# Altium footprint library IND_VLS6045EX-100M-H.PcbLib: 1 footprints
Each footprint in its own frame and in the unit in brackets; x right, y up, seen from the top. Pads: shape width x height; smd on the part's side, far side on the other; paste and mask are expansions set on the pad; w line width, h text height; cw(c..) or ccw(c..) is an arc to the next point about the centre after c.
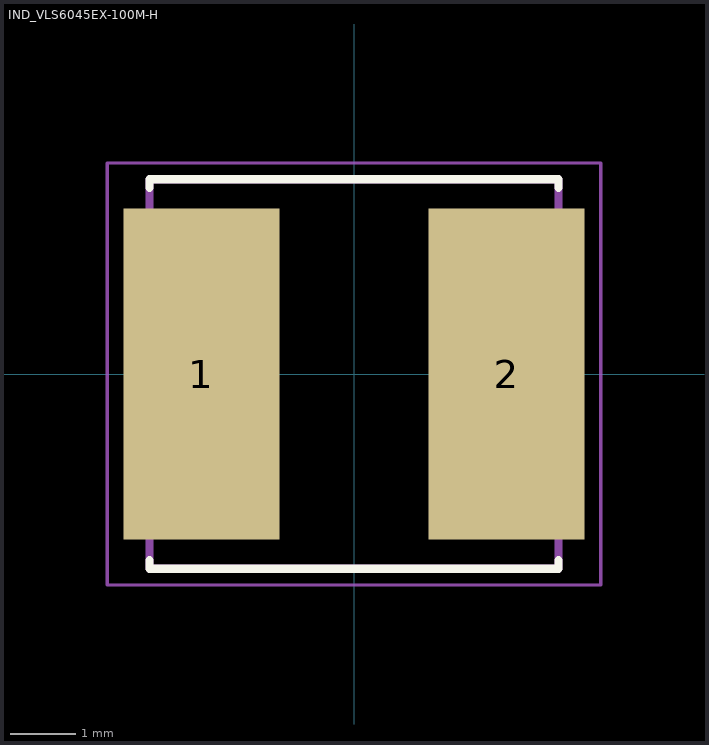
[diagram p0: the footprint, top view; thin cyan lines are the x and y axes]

## IND_VLS6045EX-100M-H [mm]
height 4.5
pads (2):
  rect 2.4x5.1 smd: 1(-2.35,0) 2(2.35,0)
Top Overlay:
  lines w0.127: -3.15,-2.87 -3.15,-3 3.15,-3 3.15,-2.87 ; -3.15,2.87 -3.15,3 3.15,3 3.15,2.87
Mechanical 13:
  lines w0.127: -3.15,-3 -3.15,3 3.15,3 3.15,-3 -3.15,-3
Mechanical 15:
  lines w0.05: -3.8,-3.25 -3.8,3.25 3.8,3.25 3.8,-3.25 -3.8,-3.25
3D body "step_temp.STEP": height 4.5, standoff 0, extent -3.15,-3 3.15,3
